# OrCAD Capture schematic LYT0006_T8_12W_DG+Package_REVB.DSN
size B; title: DER-3 X X
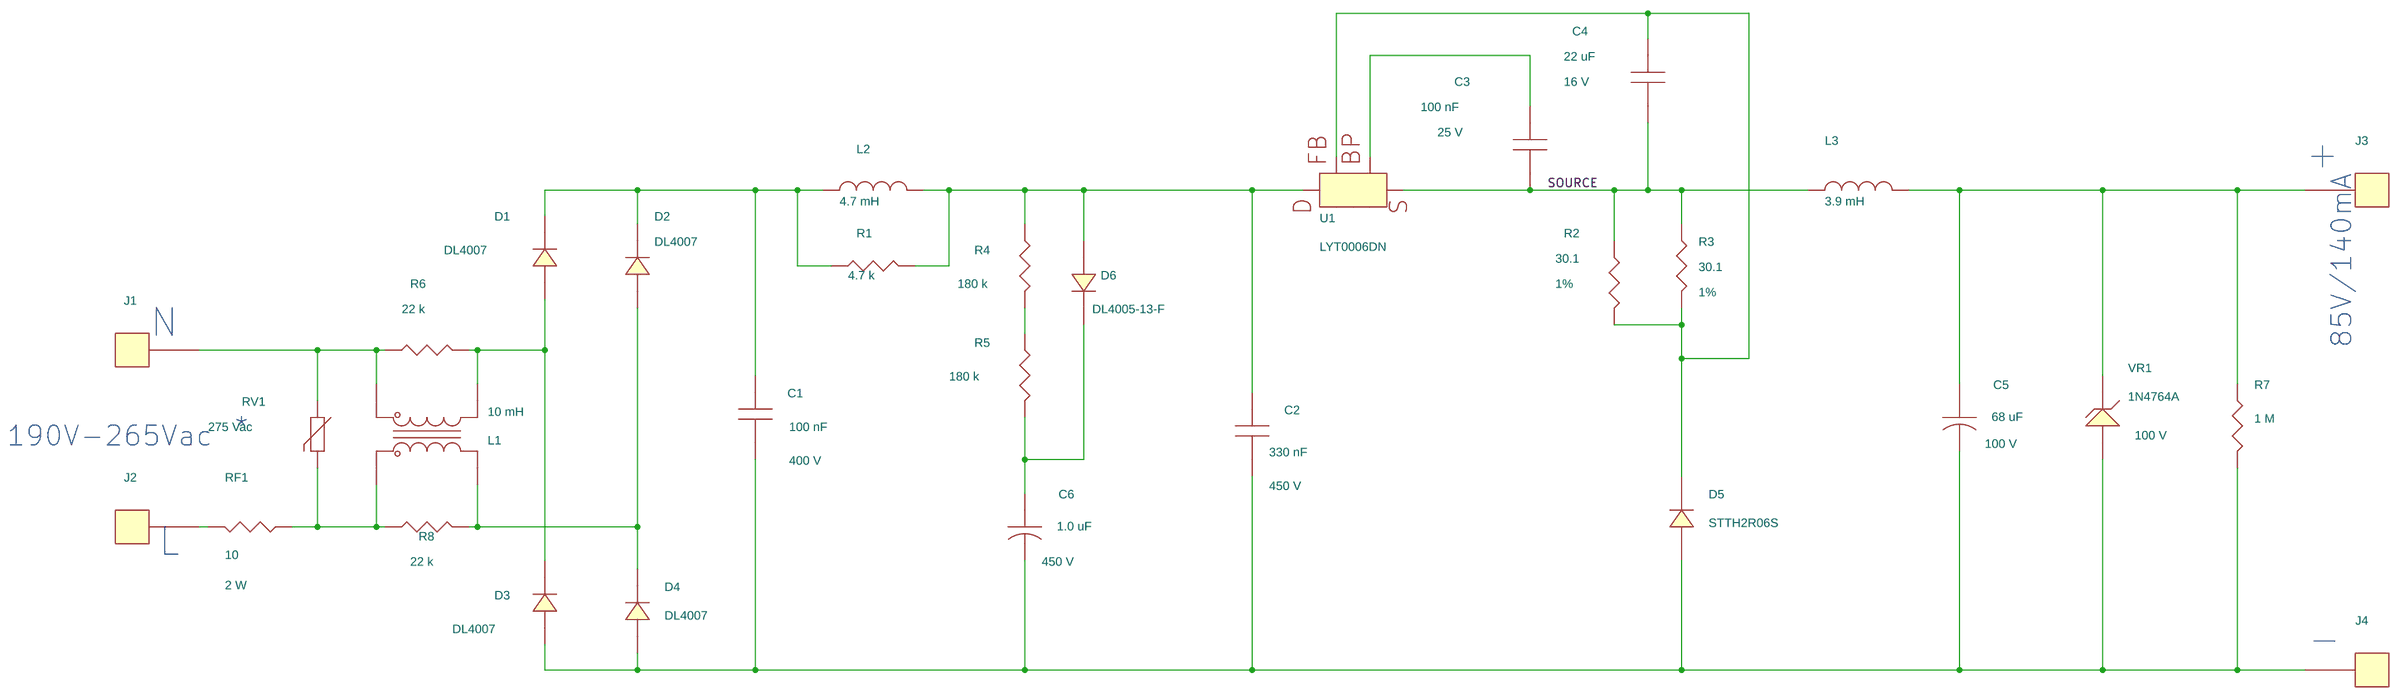
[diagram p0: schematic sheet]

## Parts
C1  100 nF  [pinpcaprad500x260400040h]
C2  330 nF  [pi_np_caprad512x299ls394d040_h]
C3  100 nF  [pismc0603]
C4  22 uF  [pismc0805]
C5  68 uF  [pipolcapclyd395x630ls200030h]
C6  1.0 uF  [pipolcapclyd320ls140030h]
D1  DL4007  [pismdmll4112]
D2  DL4007  [pismdmll4112]
D3  DL4007  [pismdmll4112]
D4  DL4007  [pismdmll4112]
D5  STTH2R06S  [pismdo214ab12]
D6  DL4005-13-F  [pismdmll4112]
J1  PCB Terminal 22 AWG  [pi_hole_22awg]
J2  PCB Terminal 22 AWG  [pi_hole_22awg]
J3  PCB Terminal 22 AWG  [pi_hole_22awg]
J4  PCB Terminal 22 AWG  [pi_hole_22awg]
L1  10 mH  [pi_sm_ind_renco_rl9250]
L2  4.7 mH  [pi_choke_450hx375ls197d030_h]
L3  3.9 mH  [pi_choke_710hx450ls290d046_h]
R1  4.7 k  [pismr0805]
R2  30.1  [pismr0805]
R3  30.1  [pismr0805]
R4  180 k  [pismr1206]
R5  180 k  [pismr1206]
R6  22 k  [pismr0805]
R7  1 M  [pismr1206]
R8  22 k  [pismr0805]
RF1  10  [pi_2w_resd145ls455d040]
RV1  275 Vac  [pi_disc_354x220_ls220x10_040_h]
U1  LYT0006DN  [piicsmdso8]
VR1  1N4764A  [pidv200x110x040do41]

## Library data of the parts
C1 = CAP_NP: Disp_Voltage: 400 V; FPLIST: pinpcaprad500x260400040,pinpcaprad500x260400040h; Part Number: 20-00368-00; Voltage: 400 V
C2 = CAP_NP: Disp_Voltage: 450 V; FPLIST: pi_np_caprad512x299ls394d040,pi_np_caprad512x299ls394d040_h; Part Number: 20-00973-00; Voltage: 450 V
C3 = CAP_NP: Disp_Voltage: 25 V; Part Number: 20-01050-00; Voltage: 25 V
C4 = CAP_NP: Disp_Voltage: 16 V; Part Number: 20-01018-00; Voltage: 16 V
C5 = CAP_POL: Disp_Voltage: 100 V; FPLIST: pipolcapcyld400ls200040,pipolcapclyd395x630ls200030h; Part Number: 20-01023-00; Voltage: 100 V
C6 = CAP_POL: Disp_Voltage: 450 V; FPLIST: pipolcapclyd320ls140030,pipolcapclyd320ls140030h; Part Number: 20-00955-00; Voltage: 450 V
D1-D4 = DIODE: Part Number: 15-00628-00
D5 = DIODE: Part Number: 15-00865-00
D6 = DIODE: Part Number: 15-00177-00
J1-J4 = TERM_1PIN: Part Number: 35-00008-00
L1 = INDUCTOR_4P_revD: Part Number: 30-00360-00
L2 = INDUCTOR: FPLIST: pi_choke_450hx375ls197d030,pi_choke_450hx375ls197d030_h; Part Number: 30-00329-00
L3 = INDUCTOR: FPLIST: pi_choke_710hx450ls290d046,pi_choke_710hx450ls290d046_h; Part Number: 30-00362-00
R1 = R: Part Number: 05-01535-00
R2 R3 = R: Disp_Tol: 1%; Part Number: 05-00538-00
R4 R5 = R: Part Number: 05-01406-00
R6 R8 = R: Part Number: 05-01551-00
R7 = R: Part Number: 05-01424-00
RF1 = R: ALT_SYMBOLS: PI_2W_RES240LS500D040,pi_2w_resd145ls455d040; Disp_Power: 2 W; FPLIST: PI_2W_VRES240LS200D040,PI_2W_RES240LS500D040,pi_2w_resd145ls455d040; Part Number: 05-05554-00
RV1 = VARISTOR: FPLIST: pi_disc_354x220_ls220x10_040,pi_disc_354x220_ls220x10_040_h; Part Number: 85-00015-00
U1 = LNK30X_SO8_DN: Part Number: 10-00752-00
VR1 = DIODE_ZENER: ALT_SYMBOLS: pidax475x125040do41,pidv200x110x040do41wbead,pidax390x125040do41; Disp_Voltage: 100 V; FPLIST: pidv200x110x040do41,pidax475x125040do41,pidv200x110x040do41wbead,pidax390x125040do41; Part Number: 15-00735-00

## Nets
SOURCE: C3.2 C4.2 L3.1 R2.1 R3.1 U1.5(S) U1.6(SOURCE) U1.7(SOURCE) U1.8(SOURCE)
N40967: C1.1 D1.1 D2.1 L2.1 R1.1
N41017: C1.2 C2.2 C5.2 C6.2 D3.2 D4.2 D5.2 J4.1 R7.2 VR1.2
N41049: C4.1 D5.1 R2.2 R3.2 U1.2(FB)
N41137: C5.1 J3.1 L3.2 R7.1 VR1.1
N41161: J1.1 L1.1 R6.1 RV1.1
N41165: L1.4 R8.1 RF1.1 RV1.2
N41193: C2.1 D6.2 L2.2 R1.2 R4.1 U1.4(D)
N41233: C3.1 U1.1(BP)
N41297: J2.1 RF1.2
N42430: D2.2 D4.1 L1.3 R8.2
N42434: D1.2 D3.1 L1.2 R6.2
N45514: R4.2 R5.1
N45535: C6.1 D6.1 R5.2

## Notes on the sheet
- +
- N
- 85V/140mA
- 190V-265Vac
- *
- L
- _
